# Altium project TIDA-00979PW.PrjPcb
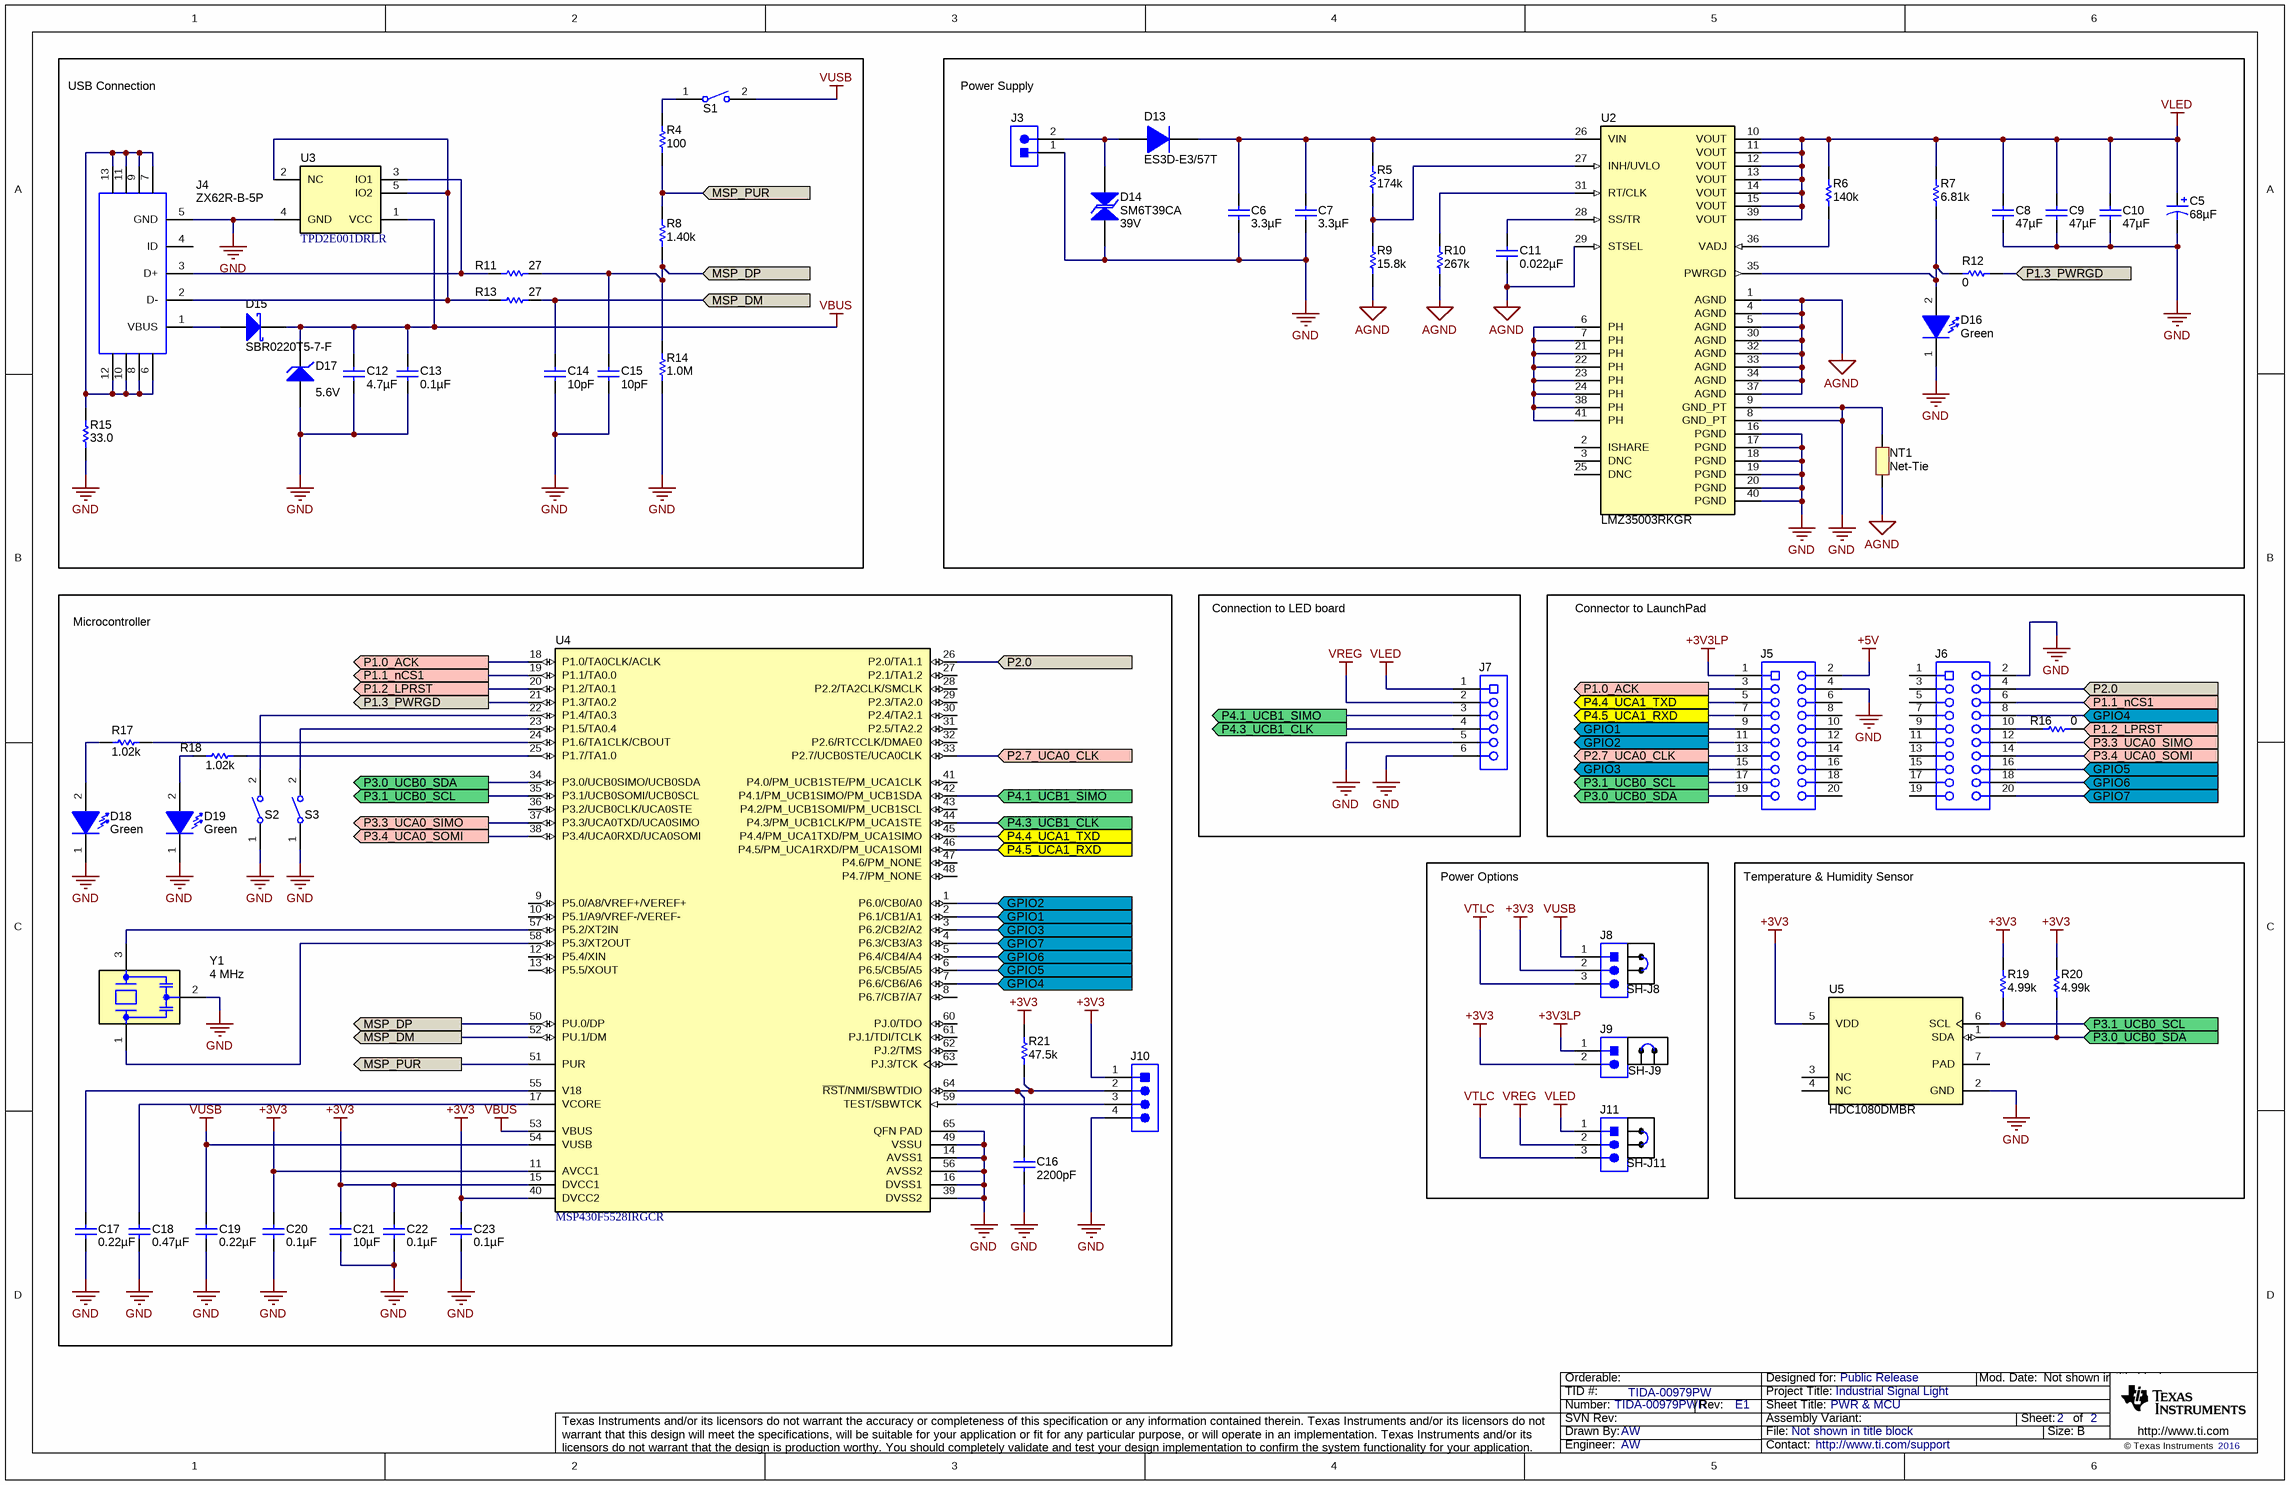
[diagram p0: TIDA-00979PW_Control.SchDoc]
CopyrightYear: 2016; PCB_Layout: GCD; PCB_Rev: E1; PRJ_Customer: Public Release; PRJ_Engineer: AW; PRJ_Number: TIDA-00979PWR; PRJ_Title: Industrial Signal Light; SCH_Rev: E1; TechSupport: http://www.ti.com/support; TID: TIDA-00979PW
2 sheets, 76 parts. Net scope: flat (ports and power ports of the same name join across sheets).
Board file: TIDA-00979PW_PCB.PcbDoc
Sheets:
  TIDA-00979PW_Control.SchDoc
  TIDA-00979PW_CoverSheet.SchDoc

## Sheet TIDA-00979PW_Control.SchDoc: PWR & MCU
size 431 x 279 mm; Date: Not shown in title block; ApprovedBy: Not shown in title block; CheckedBy: Not shown in title block; Author: Not shown in title block; CompanyName: Not shown in title block; DrawnBy: AW; Engineer: Not shown in title block; Organization: Not shown in title block; Address1: Not shown in title block; Address2: Not shown in title block; Address3: Not shown in title block; Address4: Not shown in title block; DocumentNumber: 2; Revision: Use project parameter SCH_Rev; SheetNumber: 2; SheetTotal: 2; PageSetup: Record=PageOptions¦CenterHorizontal=True¦CenterVertical=True¦PrintScale=1.00¦XCorrection=1.00¦YCorrection=1.00¦PrintKind=0¦BorderSize=5000000¦LeftOffset=0¦BottomOffset=0¦Orientation=2¦PaperLength=1000¦PaperWidth=1000¦Scale=100¦PaperSource=15¦PrintQuality=600¦MediaType=1¦DitherType=10¦PaperKind=Letter¦PrintScaleMode=1

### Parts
C5  ValueDisplayed: 68µF  [SM_RADIAL_D]  (hidden comment: EEE-FK1E680P)
C6  ValueDisplayed: 3.3µF  [1210]  (hidden comment: C3225X7S2A335M200AB)
C7  ValueDisplayed: 3.3µF  [1210]  (hidden comment: C3225X7S2A335M200AB)
C8  ValueDisplayed: 47µF  [1206_190]  (hidden comment: C3216X5R1E476M160AC)
C9  ValueDisplayed: 47µF  [1206_190]  (hidden comment: C3216X5R1E476M160AC)
C10  ValueDisplayed: 47µF  [1206_190]  (hidden comment: C3216X5R1E476M160AC)
C11  ValueDisplayed: 0.022µF  [0402S]  (hidden comment: C1005X7R1E223K)
C12  ValueDisplayed: 4.7µF  [0805_HV]  (hidden comment: GRM21BR71C475KA73L)
C13  ValueDisplayed: 0.1µF  [0402]  (hidden comment: C1005X7R1H104K050BB)
C14  ValueDisplayed: 10pF  [0402]  (hidden comment: 500R07S100JV4T)
C15  ValueDisplayed: 10pF  [0402]  (hidden comment: 500R07S100JV4T)
C16  ValueDisplayed: 2200pF  [0402]  (hidden comment: 885012205008)
C17  ValueDisplayed: 0.22µF  [0402]  (hidden comment: C1005X7R1C224K050BC)
C18  ValueDisplayed: 0.47µF  [0603]  (hidden comment: C0603C474K8RACTU)
C19  ValueDisplayed: 0.22µF  [0402]  (hidden comment: C1005X7R1C224K050BC)
C20  ValueDisplayed: 0.1µF  [0402]  (hidden comment: C1005X7R1H104K050BB)
C21  ValueDisplayed: 10µF  [0603]  (hidden comment: C1608X5R1A106M080AC)
C22  ValueDisplayed: 0.1µF  [0402]  (hidden comment: C1005X7R1H104K050BB)
C23  ValueDisplayed: 0.1µF  [0402]  (hidden comment: C1005X7R1H104K050BB)
D13  ES3D-E3/57T  [SMC]
D14  SM6T39CA  value 39V  [SMB-Bi]
D15  SBR0220T5-7-F  [SOD-523]
D16  value Green  [WL-SMCW_GREEN]  (hidden comment: 150060GS75000)
D17  value 5.6V  [SOD-123]  (hidden comment: MMSZ5232B-7-F)
D18  value Green  [WL-SMCW_GREEN]  (hidden comment: 150060GS75000)
D19  value Green  [WL-SMCW_GREEN]  (hidden comment: 150060GS75000)
J3  61300211021  [Wurth_61300211021]  (value not drawn)
J4  ZX62R-B-5P  [Hirose_ZX62R-B-5P]
J5  SSW-110-23-F-D  [CONN_SSW-110-23-F-D]  (value not drawn)
J6  SSW-110-23-F-D  [CONN_SSW-110-23-F-D]  (value not drawn)
J7  851-11-006-40-001000  [Mill-Max_851-11-006-40-001000]  (value not drawn)
J8  61300311121  [WURTH_61300311121]  (value not drawn)
J9  61300211121  [WURTH_61300211121]  (value not drawn)
J10  850-10-004-40-001000  [Mill-max_850-10-004-40-001000]  (value not drawn)
J11  61300311121  [WURTH_61300311121]  (value not drawn)
NT1  Net-Tie  [Net-Tie_10mil]  (net tie, no BOM)
R4  ValueDisplayed: 100  [0603S]  (hidden comment: CRCW0603100RFKEA)
R5  ValueDisplayed: 174k  [0402S]  (hidden comment: CRCW0402174KFKED)
R6  ValueDisplayed: 140k  [0402]  (hidden comment: CRCW0402140KFKED)
R7  ValueDisplayed: 6.81k  [0402]  (hidden comment: CRCW04026K81FKED)
R8  ValueDisplayed: 1.40k  [0402]  (hidden comment: ERJ-2RKF1401X)
R9  ValueDisplayed: 15.8k  [0402S]  (hidden comment: CRCW040215K8FKED)
R10  ValueDisplayed: 267k  [0402]  (hidden comment: CRCW0402267KFKED)
R11  ValueDisplayed: 27  [0402]  (hidden comment: CRCW040227R0JNED)
R12  ValueDisplayed: 0  [0402]  (hidden comment: CRCW04020000Z0ED)
R13  ValueDisplayed: 27  [0402]  (hidden comment: CRCW040227R0JNED)
R14  ValueDisplayed: 1.0M  [0402]  (hidden comment: CRCW04021M00JNED)
R15  ValueDisplayed: 33.0  [0603]  (hidden comment: CRCW060333R0FKEA)
R16  ValueDisplayed: 0  [0402S]  (hidden comment: CRCW04020000Z0ED)
R17  ValueDisplayed: 1.02k  [0402S]  (hidden comment: CRCW04021K02FKED)
R18  ValueDisplayed: 1.02k  [0402S]  (hidden comment: CRCW04021K02FKED)
R19  ValueDisplayed: 4.99k  [0402]  (hidden comment: CRCW04024K99FKED)
R20  ValueDisplayed: 4.99k  [0402]  (hidden comment: CRCW04024K99FKED)
R21  ValueDisplayed: 47.5k  [0402]  (hidden comment: CRCW040247K5FKED)
S1  434121025816  [SW_434121025816]  (value not drawn)
S2  434121025816  [SW_434121025816]  (value not drawn)
S3  434121025816  [SW_434121025816]  (value not drawn)
SH-J8  60900213421  [Wurth_60900213421]  (value not drawn)
SH-J9  60900213421  [Wurth_60900213421]  (value not drawn)
SH-J11  60900213421  [Wurth_60900213421]  (value not drawn)
U2  LMZ35003RKGR  [RKG0041A]
U3  TPD2E001DRLR  [DRL0005A]
U4  MSP430F5528IRGCR  [RGC0064B]
U5  HDC1080DMBR  [DMB0006A]
Y1  Frequency: 4 MHz  [Murata_CSTCR]  (hidden comment: CSTCR4M00G15L99-R0)

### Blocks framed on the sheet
USB Connection: C12-C15 D15 D17 J4 R4 R8 R11 R13-R15 S1 U3
Power Supply: C5-C11 D13 D14 D16 J3 NT1 R5-R7 R9 R10 R12 U2
Microcontroller: C16-C23 D18 D19 J10 R17 R18 R21 S2 S3 U4 Y1
Connection to LED board: J7
Connector to LaunchPad: J5 J6 R16
Power Options: J8 J9 J11 SH-J8 SH-J9 SH-J11
Temperature & Humidity Sensor: R19 R20 U5

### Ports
GPIO1, GPIO2, GPIO3, GPIO4, GPIO5, GPIO6, GPIO7, MSP_DM, MSP_DP, MSP_PUR, P1.0_ACK, P1.1_nCS1, P1.2_LPRST, P1.3_PWRGD, P2.0, P2.7_UCA0_CLK, P3.0_UCB0_SDA, P3.1_UCB0_SCL, P3.3_UCA0_SIMO, P3.4_UCA0_SOMI, P4.1_UCB1_SIMO, P4.3_UCB1_CLK, P4.4_UCA1_TXD, P4.5_UCA1_RXD

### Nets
+3V3: C20.1 C21.1 C22.1 C23.1 J8.2 J9.2 J10.1 R19.2 R20.2 R21.2 U4.11(AVCC1) U4.15(DVCC1) U4.40(DVCC2) U5.5(VDD)
+3V3LP: J5.1 J9.1
+5V: J5.2
AGND: C11.2 NT1.1 R9.1 R10.1 U2.1(AGND) U2.4(AGND) U2.5(AGND) U2.29(STSEL) U2.30(AGND) U2.32(AGND) U2.33(AGND) U2.34(AGND) U2.37(AGND)
GND: C5.2(-) C6.2 C7.2 C8.2 C9.2 C10.2 C12.2 C13.2 C14.2 C15.2 C16.2 C17.2 C18.2 C19.2 C20.2 C21.2 C22.2 C23.2 D14.1 D16.1(K) D17.2(A) D18.1(K) D19.1(K) J3.1 J4.5(GND) J5.4 J6.2 J7.5 J7.6 J10.4 NT1.2 R14.1 R15.1 S2.1 S3.1 U2.8(GND_PT) U2.9(GND_PT) U2.16(PGND) U2.17(PGND) U2.18(PGND) U2.19(PGND) U2.20(PGND) U2.40(PGND) U3.4(GND) U4.14(AVSS1) U4.16(DVSS1) U4.39(DVSS2) U4.49(VSSU) U4.56(AVSS2) U4.65(QFN_PAD) U5.2(GND) Y1.2(GND)
VBUS: C12.1 C13.1 D15.1(K) D17.1(K) U3.1(VCC) U4.53(VBUS)
VLED: C5.1(+) C8.1 C9.1 C10.1 J7.1 J11.1 R6.2 R7.2 U2.10(VOUT) U2.11(VOUT) U2.12(VOUT) U2.13(VOUT) U2.14(VOUT) U2.15(VOUT) U2.39(VOUT)
VREG: J7.2 J11.2
VTLC: J8.3 J11.3
VUSB: C19.1 J8.1 S1.2 U4.54(VUSB)
GPIO1: J5.9 U4.2(P6.1/CB1/A1) ; port GPIO1
GPIO2: J5.11 U4.1(P6.0/CB0/A0) ; port GPIO2
GPIO3: J5.15 U4.3(P6.2/CB2/A2) ; port GPIO3
GPIO4: J6.8 U4.7(P6.6/CB6/A6) ; port GPIO4
GPIO5: J6.16 U4.6(P6.5/CB5/A5) ; port GPIO5
GPIO6: J6.18 U4.5(P6.4/CB4/A4) ; port GPIO6
GPIO7: J6.20 U4.4(P6.3/CB3/A3) ; port GPIO7
MSP_DM: C14.1 R13.2 U4.52(PU.1/DM) ; port MSP_DM
MSP_DP: C15.1 R8.1 R11.2 R14.2 U4.50(PU.0/DP) ; port MSP_DP
MSP_PUR: R4.2 R8.2 U4.51(PUR) ; port MSP_PUR
P1.0_ACK: J5.3 U4.18(P1.0/TA0CLK/ACLK) ; port P1.0_ACK
P1.1_nCS1: J6.6 U4.19(P1.1/TA0.0) ; port P1.1_nCS1
P1.2_LPRST: R16.2 U4.20(P1.2/TA0.1) ; port P1.2_LPRST
P1.3_PWRGD: R12.2 U4.21(P1.3/TA0.2) ; port P1.3_PWRGD
P2.0: J6.4 U4.26(P2.0/TA1.1) ; port P2.0
P2.7_UCA0_CLK: J5.13 U4.33(P2.7/UCB0STE/UCA0CLK) ; port P2.7_UCA0_CLK
P3.0_UCB0_SDA: J5.19 R20.1 U4.34(P3.0/UCB0SIMO/UCB0SDA) U5.1(SDA) ; port P3.0_UCB0_SDA
P3.1_UCB0_SCL: J5.17 R19.1 U4.35(P3.1/UCB0SOMI/UCB0SCL) U5.6(SCL) ; port P3.1_UCB0_SCL
P3.3_UCA0_SIMO: J6.12 U4.37(P3.3/UCA0TXD/UCA0SIMO) ; port P3.3_UCA0_SIMO
P3.4_UCA0_SOMI: J6.14 U4.38(P3.4/UCA0RXD/UCA0SOMI) ; port P3.4_UCA0_SOMI
P4.1_UCB1_SIMO: J7.3 U4.42(P4.1/PM_UCB1SIMO/PM_UCB1SDA) ; port P4.1_UCB1_SIMO
P4.3_UCB1_CLK: J7.4 U4.44(P4.3/PM_UCB1CLK/PM_UCA1STE) ; port P4.3_UCB1_CLK
P4.4_UCA1_TXD: J5.5 U4.45(P4.4/PM_UCA1TXD/PM_UCA1SIMO) ; port P4.4_UCA1_TXD
P4.5_UCA1_RXD: J5.7 U4.46(P4.5/PM_UCA1RXD/PM_UCA1SOMI) ; port P4.5_UCA1_RXD
NetC6_1: C6.1 C7.1 D13.1(K) R5.2 U2.26(VIN)
NetC11_1: C11.1 U2.28(SS/TR)
NetC16_1: C16.1 J10.2 R21.1 U4.64(~{RST}/NMI/SBWTDIO)
NetC17_1: C17.1 U4.55(V18)
NetC18_1: C18.1 U4.17(VCORE)
NetD13_2: D13.2(A) D14.2 J3.2
NetD15_2: D15.2(A) J4.1(VBUS)
NetD16_2: D16.2(A) R7.1 R12.1 U2.35(PWRGD)
NetD18_2: D18.2(A) R17.2
NetD19_2: D19.2(A) R18.2
NetJ4_2: J4.2(D-) R13.1 U3.2(NC) U3.5(IO2)
NetJ4_3: J4.3(D+) R11.1 U3.3(IO1)
NetJ4_6: J4.6 J4.7 J4.8 J4.9 J4.10 J4.11 J4.12 J4.13 R15.2
NetJ6_10: J6.10 R16.1
NetJ10_3: J10.3 U4.59(TEST/SBWTCK)
NetR4_1: R4.1 S1.1
NetR5_1: R5.1 R9.2 U2.27(INH/UVLO)
NetR6_1: R6.1 U2.36(VADJ)
NetR10_2: R10.2 U2.31(RT/CLK)
NetR17_1: R17.1 U4.24(P1.6/TA1CLK/CBOUT)
NetR18_1: R18.1 U4.25(P1.7/TA1.0)
NetS2_2: S2.2 U4.22(P1.4/TA0.3)
NetS3_2: S3.2 U4.23(P1.5/TA0.4)
NetU2_6: U2.6(PH) U2.7(PH) U2.21(PH) U2.22(PH) U2.23(PH) U2.24(PH) U2.38(PH) U2.41(PH)
NetU4_57: U4.57(P5.2/XT2IN) Y1.3(Out)
NetU4_58: U4.58(P5.3/XT2OUT) Y1.1(In)

Not connected (* = marked no-connect by the designer): J4 4(ID); J5 6 8 10 12 14 16 18 20; J6 1 3 5 7 9 11 13 15 17 19; U2 2(ISHARE) 3(DNC) 25(DNC); U4 8(P6.7/CB7/A7) 9(P5.0/A8/VREF+/VEREF+) 10(P5.1/A9/VREF-/VEREF-) 12(P5.4/XIN) 13(P5.5/XOUT) 27(P2.1/TA1.2) 28(P2.2/TA2CLK/SMCLK) 29(P2.3/TA2.0) 30(P2.4/TA2.1) 31(P2.5/TA2.2) 32(P2.6/RTCCLK/DMAE0) 36(P3.2/UCB0CLK/UCA0STE) 41(P4.0/PM_UCB1STE/PM_UCA1CLK) 43(P4.2/PM_UCB1SOMI/PM_UCB1SCL) 47(P4.6/PM_NONE) 48(P4.7/PM_NONE) 60(PJ.0/TDO) 61(PJ.1/TDI/TCLK) 62(PJ.2/TMS) 63(PJ.3/TCK); U5 3(NC) 4(NC) 7(PAD)

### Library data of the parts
C5 = EEE-FK1E680P: CAP, AL, 68 µF, 25 V, +/- 20%, 0.36 ohm, SMD; Manufacturer: Panasonic; Polarized: Y; CompType: Capacitor; Value: 68uF; U/M: EA; Cap_F: 0.000068; Tolerance_%: 20; VDC_V: 25; Value2: 25V; ESR_ohm: 0.36; IRMS_A: 0.24; TaMin_C: -55; TaMax_C: 105; Cap_Case: D; AEC Category: Q200
C6 C7 = C3225X7S2A335M200AB: CAP, CERM, 3.3 µF, 100 V, +/- 20%, X7S, 1210; Manufacturer: TDK; Polarized: N; CompType: Capacitor; Value: 3.3uF; U/M: EA; Cap_F: 0.0000033; Tolerance_%: 20; Value1: Unknown; VDC_V: 100; Value2: 100V; TaMin_C: -55; TaMax_C: 125; AEC Category: Q200
C8-C10 = C3216X5R1E476M160AC: CAP, CERM, 47 µF, 25 V, +/- 20%, X5R, 1206_190; Manufacturer: TDK; Polarized: N; CompType: Capacitor; Value: 47uF; U/M: EA; Cap_F: 0.000047; Tolerance_%: 20; Value1: Unknown; VDC_V: 25; Value2: 25V; TaMin_C: -55; TaMax_C: 85; Cap_Case: 1206; AEC Category: Q200
C11 = C1005X7R1E223K: CAP, CERM, 0.022 µF, 25 V, +/- 10%, X7R, 0402; Manufacturer: TDK; Polarized: N; CompType: Capacitor; Value: 0.022uF; U/M: EA; Cap_F: 0.000000022; Tolerance_%: 10; ESR_ohm: 0.0419; Value1: 0.0419 ohm; VDC_V: 25; Value2: 25V; TaMin_C: -55; TaMax_C: 125; Cap_Case: 0402; AEC Category: Q200
C12 = GRM21BR71C475KA73L: CAP, CERM, 4.7 µF, 16 V, +/- 10%, X7R, 0805; Manufacturer: MuRata; Polarized: N; CompType: Capacitor; Value: 4.7uF; U/M: EA; Cap_F: 0.0000047; Tolerance_%: 10; ESR_ohm: 0.006; Value1: 0.006 ohm; VDC_V: 16; Value2: 16V; TaMin_C: -55; TaMax_C: 125; Cap_Case: 0805; AEC Category: Q200
C13 C20 C22 C23 = C1005X7R1H104K050BB: CAP, CERM, 0.1 µF, 50 V, +/- 10%, X7R, 0402; Manufacturer: TDK; Polarized: N; CompType: Capacitor; Value: 0.1uF; U/M: EA; Cap_F: 0.0000001; Tolerance_%: 10; Value1: Unknown; VDC_V: 50; Value2: 50V; TaMin_C: -55; TaMax_C: 125; AEC Category: Q200
C14 C15 = 500R07S100JV4T: CAP, CERM, 10 pF, 50 V, +/- 5%, C0G/NP0, 0402; Manufacturer: Johanson Technology; Polarized: N; CompType: Capacitor; Value: 10pF; U/M: EA; Cap_F: 0.00000000001; Tolerance_%: 5; Value1: Unknown; VDC_V: 50; Value2: 50V; TaMin_C: -55; TaMax_C: 125; AEC Category: Q200
C16 = 885012205008: CAP, CERM, 2200 pF, 10 V, +/- 10%, X7R, 0402; Manufacturer: Wurth Elektronik; Polarized: N; CompType: Capacitor; Value: 2200pF; U/M: EA; Cap_F: 0.0000000022; Tolerance_%: 10; Value1: Unknown; Value2: 10V; TaMin_C: -55; TaMax_C: 125; AEC Category: Q200
C17 C19 = C1005X7R1C224K050BC: CAP, CERM, 0.22 µF, 16 V, +/- 10%, X7R, 0402; Manufacturer: TDK; Polarized: N; CompType: Capacitor; Value: 0.22uF; U/M: EA; Cap_F: 0.00000022; Tolerance_%: 10; Value1: Unknown; VDC_V: 16; Value2: 16V; TaMin_C: -55; TaMax_C: 125; AEC Category: Q200
C18 = C0603C474K8RACTU: CAP, CERM, 0.47 µF, 10 V, +/- 10%, X7R, 0603; Manufacturer: Kemet; Polarized: N; CompType: Capacitor; Value: 0.47uF; U/M: EA; Cap_F: 0.00000047; Tolerance_%: 10; Value1: Unknown; Value2: 10V; TaMin_C: -55; TaMax_C: 125; AEC Category: Q200
C21 = C1608X5R1A106M080AC: CAP, CERM, 10 µF, 10 V, +/- 20%, X5R, 0603; Manufacturer: TDK; Polarized: N; CompType: Capacitor; Value: 10uF; U/M: EA; Cap_F: 0.00001; Tolerance_%: 20; ESR_ohm: 0.0078; Value1: 0.0078 ohm; VDC_V: 10; Value2: 10V; IRMS_A: 1.85; TaMin_C: -55; TaMax_C: 85; AEC Category: Q200
D13 = ES3D-E3/57T: Diode, Ultrafast, 200 V, 3 A, SMC; Manufacturer: Vishay-Semiconductor; U/M: EA; Vf_V: 0.9; Value: 200V; Value1: 3A; Value2: 0.9V; Io_A: 3; Vr_V: 200; TJmax_C: 150; AEC Category: Q101
D14 = SM6T39CA: Diode, TVS, Bi, 39 V, 600 W, SMB; Manufacturer: STMicroelectronics; U/M: EA; Power_W: 600; Vr_V: 39; Value1: 600W; RJA_CperW: 100; AEC Category: Q101
D15 = SBR0220T5-7-F: Diode, Schottky, 20 V, 0.2 A, SOD-523; Manufacturer: Diodes Inc.; U/M: EA; Vf_V: 0.47; Value: 20V; Value1: 0.2A; Value2: 0.47V; Io_A: 0.2; Vr_V: 20; AEC Category: Q101
D16 D18 D19 = 150060GS75000: LED, Green, SMD; Manufacturer: Wurth Elektronik; Type: InGaN; Vf_V: 3.2; Value2: 3.2V; Io_A: 0.02; Tjmax_C: 85; Value1: W; Angle: 140; U/M: EA
D17 = MMSZ5232B-7-F: Diode, Zener, 5.6 V, 500 mW, SOD-123; Manufacturer: Diodes Inc.; SymbolCreator: a0412235; U/M: EA; Power_W: 0.5; Vz_V: 5.6; Value1: 0.5W; RJA_CperW: 350; AEC Category: Q101
J3 = 61300211021: Header, 2.54 mm, 2x1, Gold, R/A, TH; Manufacturer: Wurth Elektronik; SymbolCreator: a0412235; Pitch_mm: 2.54; Gender: Male; Shrouded: N; Row_Count: 1
J4 = ZX62R-B-5P: Connector, Receptacle, Micro-USB Type B, SMT; Manufacturer: Hirose Electric Co. Ltd.; SymbolCreator: a0799628
J5 J6 = SSW-110-23-F-D: Connector, Receptacle, 100mil, 10x2, Gold plated, TH; Manufacturer: Samtec; SymbolCreator: a0412235
J7 = 851-11-006-40-001000: Receptacle, 50mil, 5x1, Gold, R/A, SMT; Manufacturer: Mill-Max; SymbolCreator: a0411947; Gender: Female; Row_Count: 1; Current_A: 3
J8 J11 = 61300311121: Header, 2.54 mm, 3x1, Gold, TH; Manufacturer: Wurth Elektronik; SymbolCreator: a0799628
J9 = 61300211121: Header, 2.54 mm, 2x1, Gold, TH; Manufacturer: Wurth Elektronik; SymbolCreator: a0412235
J10 = 850-10-004-40-001000: Header, 50mil, 4x1, Gold, R/A, SMT; Manufacturer: Mill-Max; SymbolCreator: a0412235
NT1 = Net-Tie: Single point connection between nets.; SymbolCreator: codlsc
R4 = CRCW0603100RFKEA: RES, 100, 1%, 0.1 W, 0603; Manufacturer: Vishay-Dale; CompType: Resistor; Value: 100; Value_Code: 100R; Tolerance_%: 1; Power_W: 0.1; Value2: 0.1W; VDC_V: 75; TempCo: 100 ppm/C; EIA_Code: E96; U/M: EA; AEC Category: Q200
R5 = CRCW0402174KFKED: RES, 174 k, 1%, 0.063 W, 0402; Manufacturer: Vishay-Dale; CompType: Resistor; Value: 174k; Res_ohm: 174000; Tolerance_%: 1; Power_W: 0.063; Value2: 0.063W; VDC_V: 50; TempCo: 100 ppm/C; EIA_Code: E96; U/M: EA; AEC Category: Q200
R6 = CRCW0402140KFKED: RES, 140 k, 1%, 0.063 W, 0402; Manufacturer: Vishay-Dale; CompType: Resistor; Value: 140k; Res_ohm: 140000; Tolerance_%: 1; Power_W: 0.063; Value2: 0.063W; VDC_V: 50; TempCo: 100 ppm/C; EIA_Code: E96; U/M: EA; AEC Category: Q200
R7 = CRCW04026K81FKED: RES, 6.81 k, 1%, 0.063 W, 0402; Manufacturer: Vishay-Dale; CompType: Resistor; Value: 6.81k; Res_ohm: 6810; Value_Code: 6k81; Tolerance_%: 1; Power_W: 0.063; Value2: 0.063W; VDC_V: 50; TempCo: 100 ppm/C; EIA_Code: E96; U/M: EA; AEC Category: Q200
R8 = ERJ-2RKF1401X: RES, 1.40 k, 1%, 0.1 W, 0402; Manufacturer: Panasonic; CompType: Resistor; Value: 1.40k; Res_ohm: 1400; Value_Code: 1k40; Tolerance_%: 1; Power_W: 0.1; Value2: 0.1W; VDC_V: 50; TempCo: 100 ppm/C; EIA_Code: E96; U/M: EA; AEC Category: Q200
R9 = CRCW040215K8FKED: RES, 15.8 k, 1%, 0.063 W, 0402; Manufacturer: Vishay-Dale; CompType: Resistor; Value: 15.8k; Res_ohm: 15800; Value_Code: 15k8; Tolerance_%: 1; Power_W: 0.063; Value2: 0.063W; VDC_V: 50; TempCo: 100 ppm/C; EIA_Code: E96; U/M: EA; AEC Category: Q200
R10 = CRCW0402267KFKED: RES, 267 k, 1%, 0.063 W, 0402; Manufacturer: Vishay-Dale; CompType: Resistor; Value: 267k; Res_ohm: 267000; Tolerance_%: 1; Power_W: 0.063; Value2: 0.063W; VDC_V: 50; TempCo: 100 ppm/C; EIA_Code: E96; U/M: EA; AEC Category: Q200
R11 R13 = CRCW040227R0JNED: RES, 27, 5%, 0.063 W, 0402; Manufacturer: Vishay-Dale; CompType: Resistor; Value: 27; Value_Code: 27R0; Tolerance_%: 5; Power_W: 0.063; Value2: 0.063W; VDC_V: 50; TempCo: 200 ppm/C; EIA_Code: E24; U/M: EA; AEC Category: Q200
R12 R16 = CRCW04020000Z0ED: RES, 0, 5%, 0.063 W, 0402; Manufacturer: Vishay-Dale; CompType: Resistor; Value: 0; Value_Code: 0000; Tolerance_%: 5; Power_W: 0.063; Value2: 0.063W; VDC_V: 50; TempCo: 200 ppm/C; EIA_Code: E24; U/M: EA; AEC Category: Q200
R14 = CRCW04021M00JNED: RES, 1.0 M, 5%, 0.063 W, 0402; Manufacturer: Vishay-Dale; CompType: Resistor; Value: 1.0Meg; Res_ohm: 1000000; Value_Code: 1M00; Tolerance_%: 5; Power_W: 0.063; Value2: 0.063W; VDC_V: 50; TempCo: 200 ppm/C; EIA_Code: E24; U/M: EA; AEC Category: Q200
R15 = CRCW060333R0FKEA: RES, 33.0, 1%, 0.1 W, 0603; Manufacturer: Vishay-Dale; CompType: Resistor; Value: 33.0; Res_ohm: 33; Value_Code: 33R0; Tolerance_%: 1; Power_W: 0.1; Value2: 0.1W; VDC_V: 75; TempCo: 100 ppm/C; U/M: EA; AEC Category: Q200
R17 R18 = CRCW04021K02FKED: RES, 1.02 k, 1%, 0.063 W, 0402; Manufacturer: Vishay-Dale; CompType: Resistor; Value: 1.02k; Res_ohm: 1020; Value_Code: 1k02; Tolerance_%: 1; Power_W: 0.063; Value2: 0.063W; VDC_V: 50; TempCo: 100 ppm/C; EIA_Code: E96; U/M: EA; AEC Category: Q200
R19 R20 = CRCW04024K99FKED: RES, 4.99 k, 1%, 0.063 W, 0402; Manufacturer: Vishay-Dale; CompType: Resistor; Value: 4.99k; Res_ohm: 4990; Value_Code: 4k99; Tolerance_%: 1; Power_W: 0.063; Value2: 0.063W; VDC_V: 50; TempCo: 100 ppm/C; EIA_Code: E96; U/M: EA; AEC Category: Q200
R21 = CRCW040247K5FKED: RES, 47.5 k, 1%, 0.063 W, 0402; Manufacturer: Vishay-Dale; CompType: Resistor; Value: 47.5k; Res_ohm: 47500; Value_Code: 47k5; Tolerance_%: 1; Power_W: 0.063; Value2: 0.063W; VDC_V: 50; TempCo: 100 ppm/C; EIA_Code: E96; U/M: EA; AEC Category: Q200
S1-S3 = 434121025816: Switch, Tactile, SPST, 12 V, SMD; Manufacturer: Wurth Elektronik; SymbolCreator: a0799628; VDC_V: 12; SwitchFunction: Off-On; PositionCount: 1; CurrentRating_mA: 50
SH-J8 SH-J9 SH-J11 = 60900213421: Shunt, 2.54mm, Gold, Black; Manufacturer: Wurth Elektronik
U2 = LMZ35003RKGR: 7-V to 50-V Input, 2.5-A Step-Down, Integrated Power Solution, RKG0041A; Alternate PartNumber: LMZ35003RKGT; Manufacturer: Texas Instruments; SymbolCreator: a0799628; CompType: IC; U/M: EA
U3 = TPD2E001DRLR: Low-Capacitance + / - 15 kV ESD-Protection Array for High-Speed Data Interfaces, 2 Channels, -40 to +85 degC, 5-pin SOT (DRL), Green (RoHS & no Sb/Br); Manufacturer: Texas Instruments; Alternate PartNumber: Equivalent; Breakdown Voltage(Min)(V): 11; IEC 61000-4-2 Air-Gap(+/- kV): 15; IEC 61000-4-2 Contact(+/- kV): 8; IO Capacitance(Typ)(pF): 1.5; IO Leakage Current(nA): 1; SubFamily: ESD Solution; USB High Speed: TRUE
U4 = MSP430F5528IRGCR: 25 MHz Mixed Signal Microcontroller with 128 KB Flash, 8192 B SRAM and 47 GPIOs, -40 to 85 degC, 64-pin QFN (RGC), Green (RoHS & no Sb/Br); Alternate Manufacturer: Texas Instruments; Alternate PartNumber: Equivalent; ADC: 12-bit SAR; ADC Channels: 16; Brown Out Reset: Yes; DMA: 3; Flash(KB): 128; Frequency(MHz): 25; GPIO: 47; Multiplier: 32x32; Pin/Package: 64DSBGA, 64VQFN, 80BGA MICROSTAR JUNIOR; SRAM(B): 8192; SubFamily: 5 Series; Timers - 16-bit: 4; USB: 1; USCI_A (UART/LIN/IrDA/SPI): 2
U5 = HDC1080DMBR: Low Power, High Accuracy Digital Humidity Sensor with Temperature Sensor, DMB0006A; Alternate PartNumber: HDC1080DMBT; Manufacturer: Texas Instruments; SymbolCreator: a0411947; CompType: IC; U/M: EA
Y1 = CSTCR4M00G15L99-R0: Resonator, 4MHz, 39pF SMD; Manufacturer: MuRata; SymbolCreator: a0799721; U/M: EA; TaMin_C: 0; TaMax_C: 70; Frequency Stability: ±0.08 %

## Sheet TIDA-00979PW_CoverSheet.SchDoc: Block Diagram
size 431 x 279 mm; Date: Not shown in title block; ApprovedBy: Not shown in title block; CheckedBy: Not shown in title block; Author: Not shown in title block; CompanyName: Not shown in title block; DrawnBy: AW; Engineer: Not shown in title block; Organization: Not shown in title block; Address1: Not shown in title block; Address2: Not shown in title block; Address3: Not shown in title block; Address4: Not shown in title block; DocumentNumber: 1; Revision: Use project parameter SCH_Rev; SheetNumber: 1; SheetTotal: 2; PageSetup: Record=PageOptions¦CenterHorizontal=True¦CenterVertical=True¦PrintScale=1.00¦XCorrection=1.00¦YCorrection=1.00¦PrintKind=0¦BorderSize=5000000¦LeftOffset=0¦BottomOffset=0¦Orientation=2¦PaperLength=1000¦PaperWidth=1000¦Scale=100¦PaperSource=15¦PrintQuality=600¦MediaType=1¦DitherType=10¦PaperKind=Letter¦PrintScaleMode=1
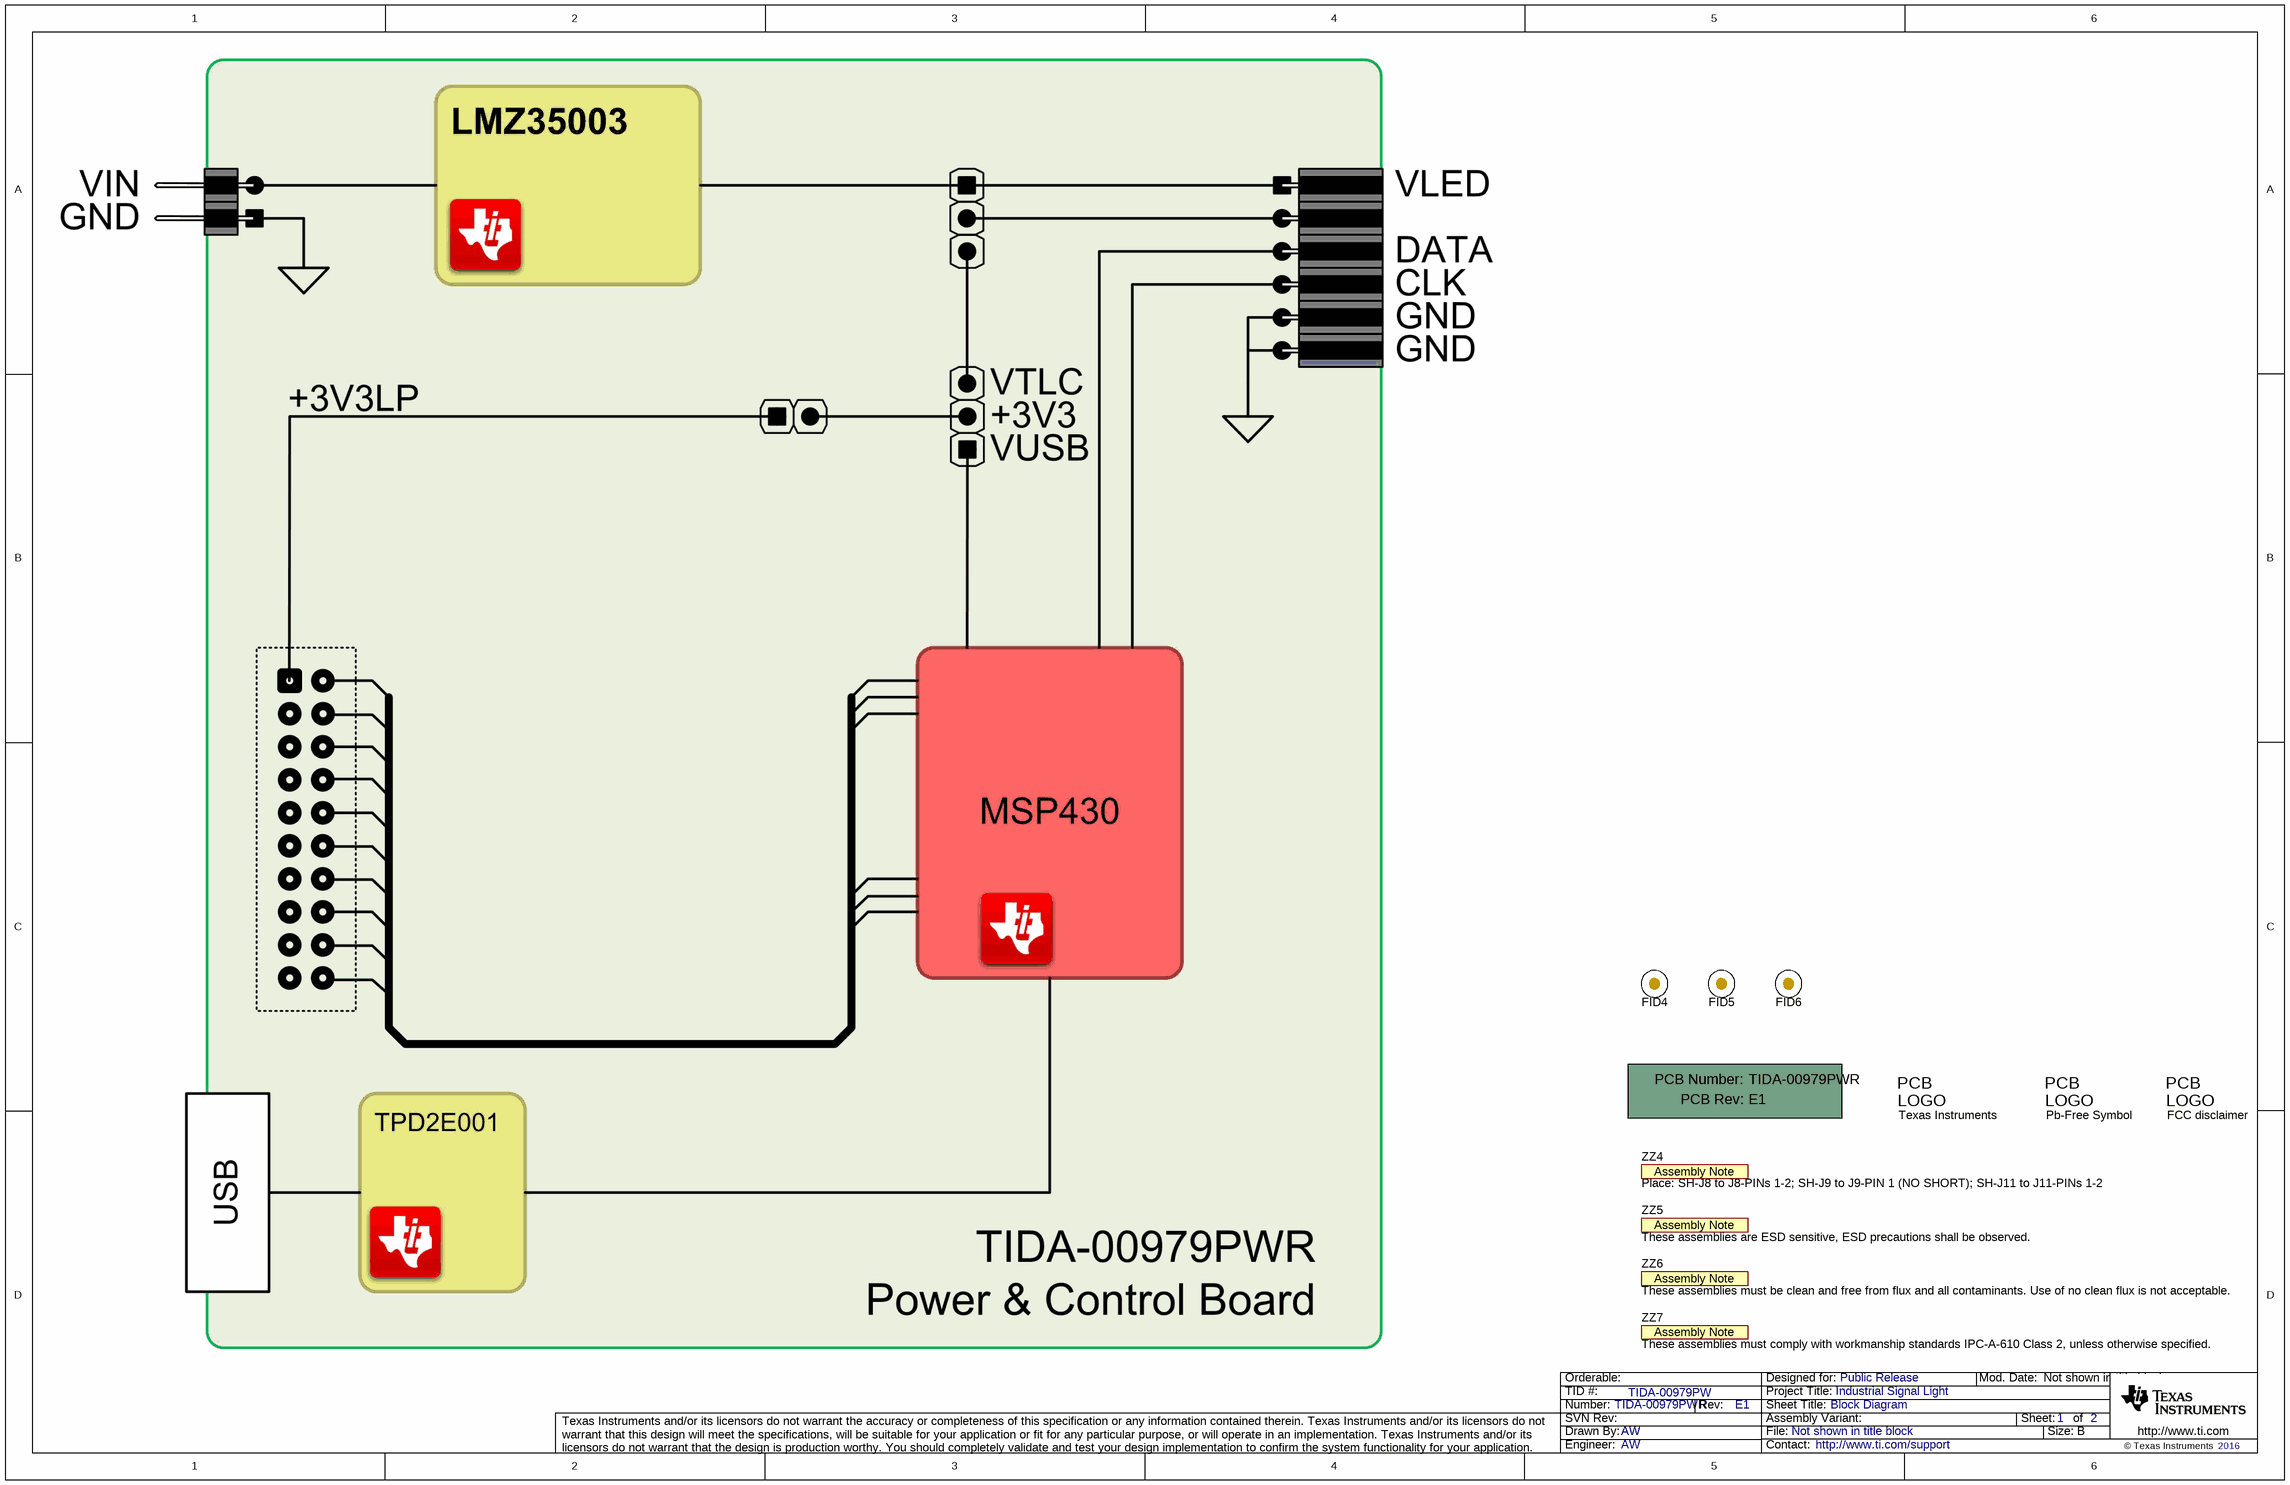
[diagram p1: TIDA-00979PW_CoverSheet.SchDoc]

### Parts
!PCB2  Printed Circuit Board  (value not drawn)  (mechanical)
FID4  Fiducial  [Fiducial10-20]  (value not drawn)
FID5  Fiducial  [Fiducial10-20]  (value not drawn)
FID6  Fiducial  [Fiducial10-20]  (value not drawn)
Logo4  Texas Instruments  [TI_Stacked_Overlay_Small]  (no BOM)
Logo5  Pb-Free Symbol  [Pb-Free_Overlay_Small]  (no BOM)
Logo6  FCC disclaimer  [FCC_disclaimer]  (no BOM)
ZZ4  Place: SH-J8 to J8-PINs 1-2; SH-J9 to J9-PIN 1 (NO SHORT); SH-J11 to J11-PINs 1-2  [AssemblyNote]  (no BOM)
ZZ5  These assemblies are ESD sensitive, ESD precautions shall be observed.  [AssemblyNote]  (no BOM)
ZZ6  These assemblies must be clean and free from flux and all contaminants. Use of no clean flux is not acceptable.  [AssemblyNote]  (no BOM)
ZZ7  These assemblies must comply with workmanship standards IPC-A-610 Class 2, unless otherwise specified.  [AssemblyNote]  (no BOM)

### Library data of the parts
!PCB2 = PCB: Manufacturer: Any; PartNumber: TIDA-00979PWR; SymbolCreator: a0412235
FID4-FID6 = Fiducial: Fiducial mark.  There is nothing to buy or mount.; SymbolCreator: codlsc
Logo4 = TI_Logo: Texas Instrument Corporate Signature; SymbolCreator: codlsc
Logo5 = Pb-Free: SymbolCreator: a0412235
Logo6 = FCC_disclaimer: SymbolCreator: codlsc
ZZ4 = Assembly Note: SymbolCreator: codlsc
ZZ5-ZZ7 = AssemblyNote: SymbolCreator: codlsc

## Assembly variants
TID: not fitted C16 FID4 FID5 FID6 R16
EVM: not fitted C16 FID4 FID5 FID6 R16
